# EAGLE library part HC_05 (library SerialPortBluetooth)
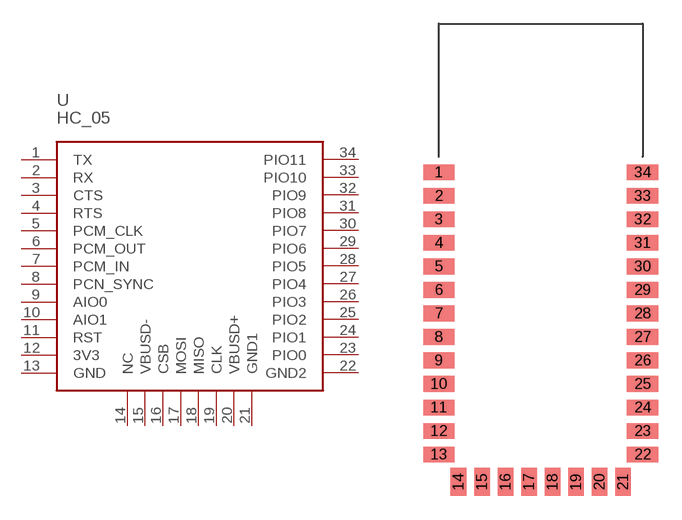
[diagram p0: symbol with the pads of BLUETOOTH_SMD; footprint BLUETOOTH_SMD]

Designator prefix U

## HC_05  [BLUETOOTH_SMD]
1  TX
2  RX
3  CTS
4  RTS
5  PCM_CLK
6  PCM_OUT
7  PCM_IN
8  PCN_SYNC
9  AIO0
10  AIO1
11  RST
12  3V3
13  GND
14  NC
15  VBUSD-
16  CSB
17  MOSI
18  MISO
19  CLK
20  VBUSD+
21  GND1
22  GND2
23  PIO0
24  PIO1
25  PIO2
26  PIO3
27  PIO4
28  PIO5
29  PIO6
30  PIO7
31  PIO8
32  PIO9
33  PIO10
34  PIO11

## Footprint BLUETOOTH_SMD (pad centres in mm)
smd 2 x 1: 1 0,0; 2 0,-1.5; 3 0,-3; 4 0,-4.5; 5 0,-6; 6 0,-7.5; 7 0,-9; 8 0,-10.5; 9 0,-12; 10 0,-13.5; 11 0,-15; 12 0,-16.5; 13 0,-18; 22 13,-18; 23 13,-16.5; 24 13,-15; 25 13,-13.5; 26 13,-12; 27 13,-10.5; 28 13,-9; 29 13,-7.5; 30 13,-6; 31 13,-4.5; 32 13,-3; 33 13,-1.5; 34 13,0
smd 1 x 1.8: 14 1.25,-19.75; 15 2.75,-19.75; 16 4.25,-19.75; 17 5.75,-19.75; 18 7.25,-19.75; 19 8.75,-19.75; 20 10.25,-19.75; 21 11.75,-19.75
